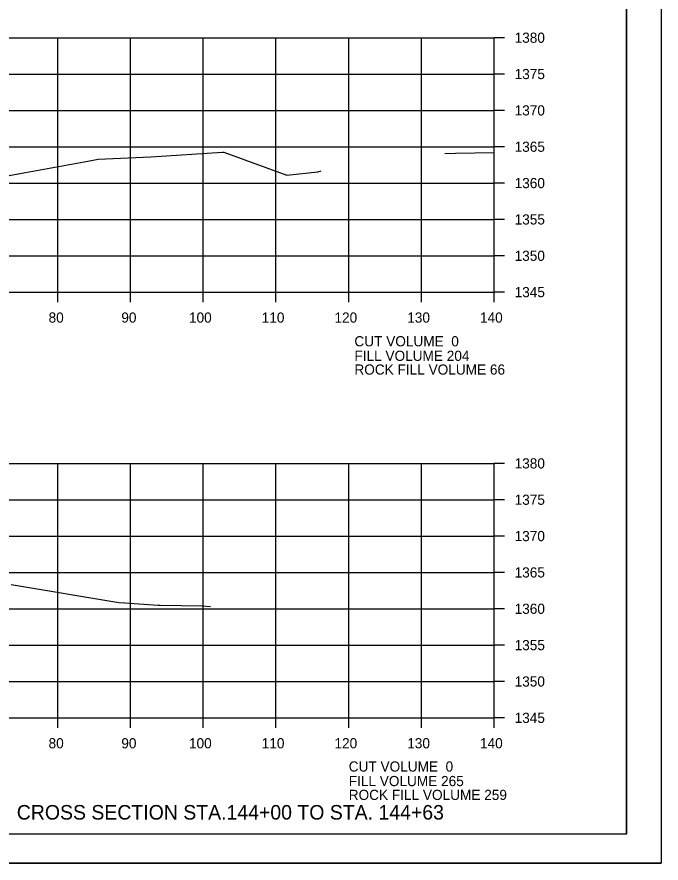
# Model space of a CAD drawing. Extents: x 1374311 to 1383814, y 384102 to 406278.
# Drawn here: x 1381703.1 to 1381791.6, y 390084.7 to 390201.1 of the extents above; entities that cross this region are included whole.
import ezdxf

# ---------------------------------------------------------------- set-up
doc = ezdxf.new("R2010")
doc.units = 0
for name, color, linetype in [('R_Axis', 7, 'Continuous'), ('R_Axis Annot', 7, 'Continuous'), ('R_Border', 7, 'Continuous'), ('R_Draft', 7, 'Continuous'), ('R_Exist Surface', 7, 'Continuous'), ('R_Grid', 7, 'Continuous'), ('R_No Plot', 7, 'Continuous')]:
    doc.layers.add(name, color=color, linetype=linetype)

msp = doc.modelspace()

# ---------------------------------------------------------------- linework, layer by layer
at = {"layer": 'R_Axis'}
for p, q in [((1381768.66, 390163.27), (1381768.66, 390198.27)), ((1381770.06, 390198.27), (1381768.66, 390198.27)), ((1381770.06, 390193.27), (1381768.66, 390193.27)), ((1381770.06, 390188.27), (1381768.66, 390188.27)), ((1381770.06, 390183.27), (1381768.66, 390183.27)), ((1381770.06, 390178.27), (1381768.66, 390178.27)), ((1381770.06, 390173.27), (1381768.66, 390173.27)), ((1381770.06, 390168.27), (1381768.66, 390168.27)), ((1381488.66, 390163.27), (1381768.66, 390163.27)), ((1381708.66, 390161.87), (1381708.66, 390163.27)), ((1381718.66, 390161.87), (1381718.66, 390163.27)), ((1381728.66, 390161.87), (1381728.66, 390163.27)), ((1381738.66, 390161.87), (1381738.66, 390163.27)), ((1381748.66, 390161.87), (1381748.66, 390163.27)), ((1381758.66, 390161.87), (1381758.66, 390163.27)), ((1381768.66, 390161.87), (1381768.66, 390163.27)), ((1381770.06, 390163.27), (1381768.66, 390163.27)), ((1381768.66, 390104.71), (1381768.66, 390139.71)), ((1381770.06, 390139.71), (1381768.66, 390139.71)), ((1381770.06, 390134.71), (1381768.66, 390134.71)), ((1381770.06, 390129.71), (1381768.66, 390129.71)), ((1381770.06, 390124.71), (1381768.66, 390124.71)), ((1381770.06, 390119.71), (1381768.66, 390119.71)), ((1381770.06, 390114.71), (1381768.66, 390114.71)), ((1381770.06, 390109.71), (1381768.66, 390109.71)), ((1381488.66, 390104.71), (1381768.66, 390104.71)), ((1381708.66, 390103.31), (1381708.66, 390104.71)), ((1381718.66, 390103.31), (1381718.66, 390104.71)), ((1381728.66, 390103.31), (1381728.66, 390104.71)), ((1381738.66, 390103.31), (1381738.66, 390104.71)), ((1381748.66, 390103.31), (1381748.66, 390104.71)), ((1381758.66, 390103.31), (1381758.66, 390104.71)), ((1381768.66, 390103.31), (1381768.66, 390104.71)), ((1381770.06, 390104.71), (1381768.66, 390104.71))]:
    msp.add_line(p, q, dxfattribs=at)
at = {"layer": 'R_Border'}
for q in [(1381786.84, 390294.17), (1381470.66, 390088.71)]:
    msp.add_line((1381786.84, 390088.71), q, dxfattribs=at)
at = {"layer": 'R_Exist Surface'}
for points in [[(1381697.16, 390178.42), (1381704.21, 390179.72), (1381712.78, 390181.29), (1381714.2, 390181.57), (1381721.44, 390181.89), (1381731.3, 390182.53), (1381731.37, 390182.54), (1381731.41, 390182.54), (1381731.51, 390182.51), (1381740.14, 390179.36), (1381744.4, 390179.8), (1381744.86, 390179.95)], [(1381761.86, 390182.35), (1381763.34, 390182.38), (1381768.66, 390182.47)], [(1381702.26, 390123.04), (1381717.07, 390120.59), (1381717.9, 390120.52), (1381722.42, 390120.19), (1381722.61, 390120.22), (1381722.74, 390120.2), (1381728.52, 390120.1), (1381729.64, 390120.01)]]:
    msp.add_lwpolyline(points, dxfattribs=at)
at = {"layer": 'R_Grid'}
for p, q in [((1381488.66, 390198.27), (1381768.66, 390198.27)), ((1381708.66, 390163.27), (1381708.66, 390198.27)), ((1381718.66, 390163.27), (1381718.66, 390198.27)), ((1381728.66, 390163.27), (1381728.66, 390198.27)), ((1381738.66, 390163.27), (1381738.66, 390198.27)), ((1381748.66, 390163.27), (1381748.66, 390198.27)), ((1381758.66, 390163.27), (1381758.66, 390198.27)), ((1381768.66, 390163.27), (1381768.66, 390198.27)), ((1381488.66, 390193.27), (1381768.66, 390193.27)), ((1381488.66, 390188.27), (1381768.66, 390188.27)), ((1381488.66, 390183.27), (1381768.66, 390183.27)), ((1381488.66, 390178.27), (1381768.66, 390178.27)), ((1381488.66, 390173.27), (1381768.66, 390173.27)), ((1381488.66, 390168.27), (1381768.66, 390168.27)), ((1381488.66, 390163.27), (1381768.66, 390163.27)), ((1381488.66, 390139.71), (1381768.66, 390139.71)), ((1381708.66, 390104.71), (1381708.66, 390139.71)), ((1381718.66, 390104.71), (1381718.66, 390139.71)), ((1381728.66, 390104.71), (1381728.66, 390139.71)), ((1381738.66, 390104.71), (1381738.66, 390139.71)), ((1381748.66, 390104.71), (1381748.66, 390139.71)), ((1381758.66, 390104.71), (1381758.66, 390139.71)), ((1381768.66, 390104.71), (1381768.66, 390139.71)), ((1381488.66, 390134.71), (1381768.66, 390134.71)), ((1381488.66, 390129.71), (1381768.66, 390129.71)), ((1381488.66, 390124.71), (1381768.66, 390124.71)), ((1381488.66, 390119.71), (1381768.66, 390119.71)), ((1381488.66, 390114.71), (1381768.66, 390114.71)), ((1381488.66, 390109.71), (1381768.66, 390109.71)), ((1381488.66, 390104.71), (1381768.66, 390104.71))]:
    msp.add_line(p, q, dxfattribs=at)
at = {"layer": 'R_No Plot'}
msp.add_line((1381458.26, 390084.73), (1381791.59, 390084.73), dxfattribs=at)
for points in [[(1381458.25, 390298.06), (1381791.59, 390298.06), (1381791.59, 390084.73), (1381458.25, 390084.73)], [(1381704.58, 390294.17), (1381704.58, 390284.29), (1381740.31, 390284.29), (1381740.31, 390281.37), (1381763.51, 390281.37), (1381763.51, 390258.15), (1381786.84, 390258.15), (1381786.84, 390088.71), (1381470.66, 390088.71), (1381470.66, 390294.17)]]:
    msp.add_lwpolyline(points, close=True, dxfattribs=at)

# ---------------------------------------------------------------- texts
at = {"layer": 'R_Axis Annot'}
for s, p in [('1380', (1381771.46, 390197.57)), ('1375', (1381771.46, 390192.57)), ('1370', (1381771.46, 390187.57)), ('1365', (1381771.46, 390182.57)), ('1360', (1381771.46, 390177.57)), ('1355', (1381771.46, 390172.57)), ('1350', (1381771.46, 390167.57)), ('1345', (1381771.46, 390162.57)), ('80', (1381707.4, 390159.07)), ('90', (1381717.4, 390159.07)), ('100', (1381726.7, 390159.07)), ('110', (1381736.7, 390159.07)), ('120', (1381746.7, 390159.07)), ('130', (1381756.7, 390159.07)), ('140', (1381766.7, 390159.07)), ('CUT VOLUME  0', (1381749.44, 390155.81)), ('FILL VOLUME 204', (1381749.44, 390153.81)), ('ROCK FILL VOLUME 66', (1381749.44, 390151.92)), ('1380', (1381771.46, 390139.01)), ('1375', (1381771.46, 390134.01)), ('1370', (1381771.46, 390129.01)), ('1365', (1381771.46, 390124.01)), ('1360', (1381771.46, 390119.01)), ('1355', (1381771.46, 390114.01)), ('1350', (1381771.46, 390109.01)), ('1345', (1381771.46, 390104.01)), ('80', (1381707.4, 390100.51)), ('90', (1381717.4, 390100.51)), ('100', (1381726.7, 390100.51)), ('110', (1381736.7, 390100.51)), ('120', (1381746.7, 390100.51)), ('130', (1381756.7, 390100.51)), ('140', (1381766.7, 390100.51)), ('CUT VOLUME  0', (1381748.66, 390097.31)), ('FILL VOLUME 265', (1381748.66, 390095.31)), ('ROCK FILL VOLUME 259', (1381748.66, 390093.41))]:
    msp.add_text(s, height=1.4, dxfattribs=at).set_placement(p)
at = {"layer": 'R_Draft'}
msp.add_text('CROSS SECTION STA.144+00 TO STA. 144+63', height=2, dxfattribs=at).set_placement((1381703.03, 390090.71))

doc.saveas('drawing.dxf')
